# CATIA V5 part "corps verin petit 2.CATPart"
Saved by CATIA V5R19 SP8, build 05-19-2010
Part number: corps verin petit 2
Bounding box of the stored display mesh (mm): x -6.642 to 19.911, y -54 to -48, z 98.028 to 139.838
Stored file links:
  G:\EU_thinkMotion\CFAO_2010\MMS_groupe1\MMS_groupe1\A reprendre\OK\glenerrant\glenerrant\glenerrant\corps verin petit 2.CATPart
  C:\Users\Gauthier\Documents\IFMA\Projet CFAO\Systeme.CATProduct
  G:\EU_thinkMotion\CFAO_2010\MMS_groupe1\MMS_groupe1\A reprendre\OK\glenerrant\glenerrant\glenerrant\Corps verin3.CATPart
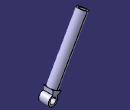
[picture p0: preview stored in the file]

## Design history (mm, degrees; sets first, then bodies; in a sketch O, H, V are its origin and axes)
Set1
  Plane1: linked copy from another document
Set2
  Point1: (17, -51, 101)
  Point2: (-9, -51, 147)
  Point3: (17, 51, 101)
  Line1: type PtPt, FirstPoint Point1, SecondPoint Point2
  Line2: type PtPt, FirstPoint Point1, SecondPoint Point3
  Plane2: type Normal, Curve Line1, RefPoint Point1
Body1 (main body)
  Sketch1 on Plane1, origin (0, -51, 0), H (-1, 0, 0), V (0, 0, 1)
    arc A1 centre (-17, 101) radius 3 from (-17.0779, 103.999) to (-14.3905, 102.48) ccw
    point P1 (-17, 101)
    circle A2 centre (-17, 101) radius 2
    point P2 (-17, 101)
    reference projected point E1 (-17, 101) from Point1
    reference projected point E2 (-17, 101) from Point1
    line L1 (-14.3905, 102.48) -> (-11.928, 103.8766)
    point P4 (-11.928, 103.8766)
    line L2 (-17.0779, 103.999) -> (-17.1514, 106.829)
    line L3 (-17.1514, 106.829) -> (-11.928, 103.8766)
    point P7 (-11.928, 103.8766)
    reference intersected line E3 through (39.149, 69.2636) direction (-0.8706, 0.4921) from Plane2
    reference projected point E4 (-17, 101) from Point1
    reference projected point E5 (-17, 101) from Point1
    reference intersected line E6 through (39.149, 69.2636) direction (-0.8706, 0.4921) from Plane2
    reference projected line E7 (-17, 101) -> (9, 147) from Line1
    radius A2 = 2
    radius A1 = 3
    length L3 = 6
    distance L3 E6 = 5
    distance P4 E7 = 3
    coincidence: E1 P1, E2 P2, L3 P4, L2 E4, L1 E5, P4 P7
    parallelism: L3 E3
  Pad1: profile Sketch1, direction (0, 1, 0), length 3, opposite side length 3
  Sketch2 on Plane2, origin (-39.149, 0, 69.2636), H (0, -1, 0), V (0.8706, 0, 0.4921)
    circle A1 centre (51, 64.4974) radius 3
    point P1 (51, 64.4974)
    circle A2 centre (51, 64.4974) radius 2
    point P2 (51, 64.4974)
    reference projected point E1 (51, 64.4974) from Point1
    reference projected point E2 (51, 64.4974) from Point1
    radius A2 = 2
    radius A1 = 3
    coincidence: P1 E1, P2 E2
  Pad2: profile Sketch2, direction (-0.4921, 0, 0.8706), length 43, opposite side length -5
